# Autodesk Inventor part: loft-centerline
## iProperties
Shininess: 77.0
Angle Display Precision: 2
Document Length Units: 11269
Document Angle Units: 11279
Document Time Units: 11290
Document Mass Units: 11283
Document Length Units Precision: 3
Document Angle Units Precision: 2
Created: 2001-12
Part Number: loft-centerline
Document SubType Name: Modeling
Designer: CADSoft
Density: 0.0
Volumn: 0.0
Area: 0.0
PropertySet Name: Model Information
Control State: 0
Master: False
Checked Out: False
Author: CADSoft
